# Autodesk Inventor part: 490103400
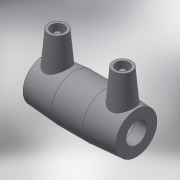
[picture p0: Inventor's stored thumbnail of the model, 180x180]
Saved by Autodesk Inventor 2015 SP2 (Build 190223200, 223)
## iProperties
Created: 2017-06
Part Number: 490103400
Material: Generic
Description: PLASSON COUPLER 400-400
Document SubType Name: Modeling
Designer: KIM
Mass: 55.0731 g
Surface Area: 148.067 cm^2
Volume: 55.0731 cm^3
Density: 1 g/cm^3
Appearance: Default
Author: KIM
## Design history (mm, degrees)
derived "490104.ipt"
feature "Solid1::490104.ipt"
tag "TaggingFeature1"
body "Solid1"
other parameters: "d0" = 293, "d2" = 485, "d3" = 145, "d4" = 97.66667, "d5" = 436.5, "d8" = 168 deg, "d10" = 58, "d11" = 19.33333, "d13" = 293, "d14" = 17.6296, "d15" = 145, "d16" = 145, "d19" = 3.52592, "d20" = 168 deg, "d22" = 455.9, "d23" = 485, "d24" = 442.223, "d25" = 135 deg, "d26" = 161.15, "d27" = 135 deg, "d29" = 231, "d30" = 14, "d31" = 102.55, "d34" = 5 deg, "d35" = 15, "d39" = 5 deg, "d41" = 4, "d42" = 14, "d43" = 0, "d45" = 4, "d46" = 14, "d47" = 0, "d48" = 3, "d49" = 0, "d50" = 3, "d51" = 0, "d52" = 42.05, "d53" = 10.5125, "L_" = 293, "L_1" = 145, "D_" = 485, "A_" = 231, "d_2" = 12
